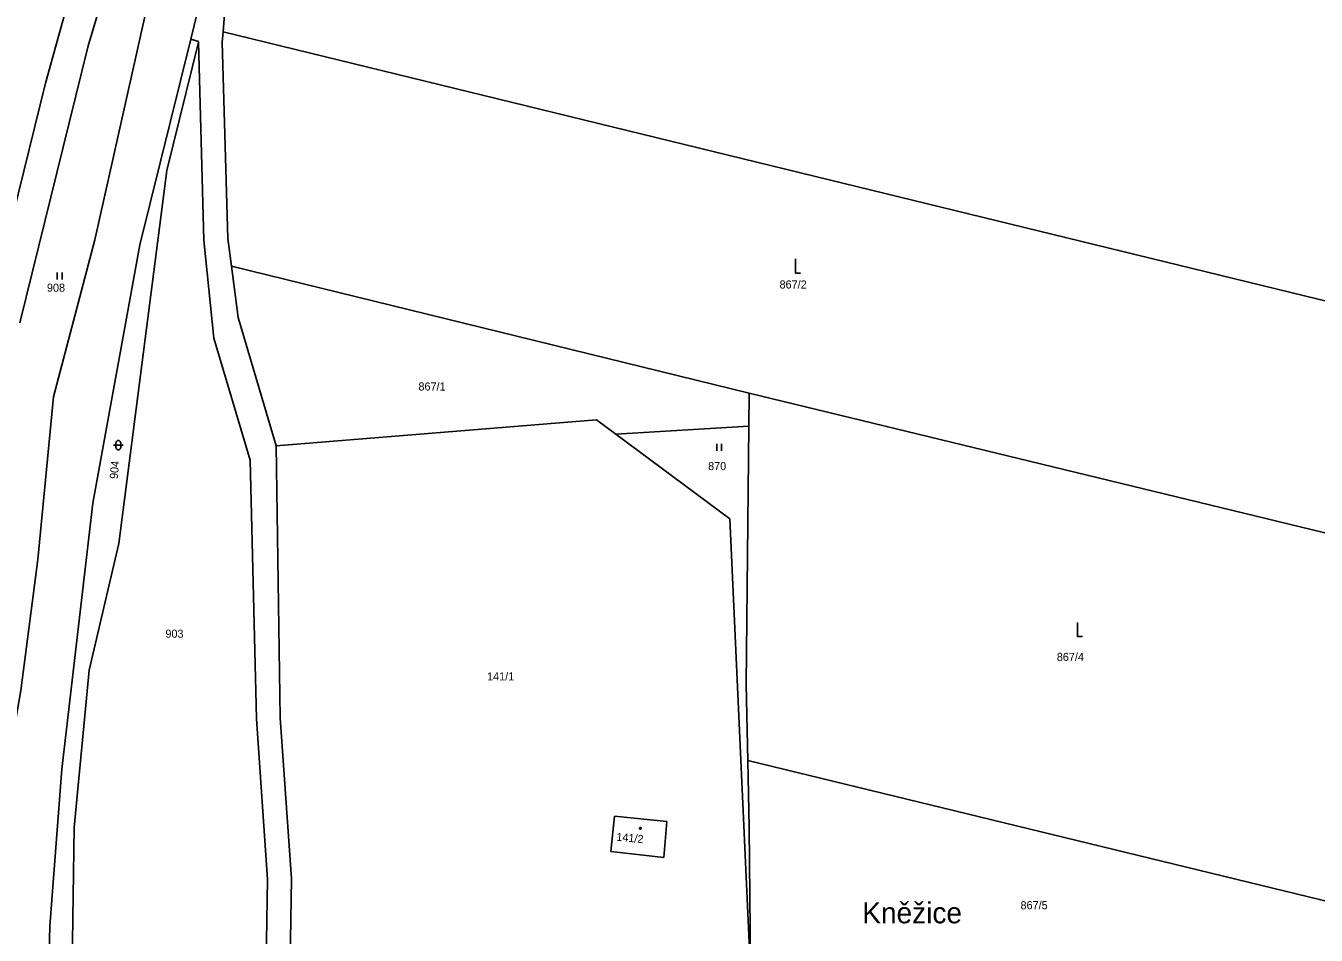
# Model space of a CAD drawing. Extents: x -812394 to -807601, y -1013097 to -1009266.
# Drawn here: x -809883 to -809612.2, y -1010592.7 to -1010401.8 of the extents above; entities that cross this region are included whole.
import ezdxf

# ---------------------------------------------------------------- set-up
doc = ezdxf.new("R2010")
doc.units = 0
for name, color, linetype in [('Default', 7, 'Continuous'), ('KN_HRANICE', 7, 'Continuous'), ('KN_KULTURY', 7, 'Continuous'), ('KN_PARCELY', 7, 'Continuous')]:
    doc.layers.add(name, color=color, linetype=linetype)

# ---------------------------------------------------------------- blocks, each defined once
blk = doc.blocks.new('302')
at = {"layer": 'Default'}
blk.add_lwpolyline([(0, 3), (0, 0), (1, 0)], dxfattribs=at)
blk = doc.blocks.new('306')
at = {"layer": 'Default'}
for p, q in [((-0.5, 1.5), (-0.5, 0)), ((0.5, 0), (0.5, 1.5))]:
    blk.add_line(p, q, dxfattribs=at)
blk = doc.blocks.new('316')
at = {"layer": 'Default'}
for points in [[(-1, 1), (0.27, 1), (1, 1)], [(-0.5, 1.5), (-0.4, 1.79), (-0.15, 1.97), (0.16, 1.97), (0.41, 1.79), (0.51, 1.5), (0.51, 0.5), (0.41, 0.21), (0.16, 0.03), (-0.15, 0.03), (-0.4, 0.21), (-0.5, 0.5), (-0.5, 1.5)]]:
    blk.add_lwpolyline(points, dxfattribs=at)
blk = doc.blocks.new('402')
at = {"layer": 'Default'}
blk.add_lwpolyline([(0.09, 0.15), (0.18, 0), (0.09, -0.15), (-0.09, -0.15), (-0.18, 0), (-0.09, 0.15), (0.09, 0.15)], dxfattribs=at)

msp = doc.modelspace()

# ---------------------------------------------------------------- linework, layer by layer
at = {"layer": 'KN_HRANICE'}
for p, q in [((-809864.27, -1010361.43), (-809878.82, -1010413.89)), ((-809869.89, -1010406.06), (-809858.75, -1010368.45)), ((-809842.4, -1010380.57), (-809848.37, -1010404.67)), ((-809841.57, -1010403.09), (-809840.96, -1010395.38)), ((-809841.74, -1010405.27), (-809841.57, -1010403.09)), ((-809714.42, -1010434.16), (-809841.57, -1010403.09)), ((-809884.23, -1010464.16), (-809869.89, -1010406.06)), ((-809848.37, -1010404.67), (-809859.05, -1010447.8)), ((-809853.38, -1010432.24), (-809846.74, -1010405.27)), ((-809848.37, -1010404.67), (-809846.74, -1010405.14)), ((-809846.74, -1010405.14), (-809846.74, -1010405.27)), ((-809846.74, -1010405.27), (-809845.6, -1010446.84)), ((-809840.6, -1010446.52), (-809841.74, -1010405.27)), ((-809878.82, -1010413.89), (-809894.45, -1010477.13)), ((-809863.41, -1010510.51), (-809853.38, -1010432.24)), ((-809587.27, -1010465.23), (-809714.42, -1010434.16)), ((-809845.6, -1010446.84), (-809843.49, -1010467.38)), ((-809840.6, -1010446.52), (-809839.82, -1010452.31)), ((-809859.05, -1010447.8), (-809868.93, -1010502.05)), ((-809839.82, -1010452.31), (-809838.38, -1010463.06)), ((-809839.82, -1010452.31), (-809731.16, -1010478.93)), ((-809830.46, -1010490), (-809838.38, -1010463.06)), ((-809843.49, -1010467.38), (-809835.86, -1010493.01)), ((-809731.16, -1010478.93), (-809731.23, -1010485.87)), ((-809731.16, -1010478.93), (-809588.81, -1010513.56)), ((-809763.21, -1010484.53), (-809830.46, -1010490)), ((-809759.15, -1010487.55), (-809763.21, -1010484.53)), ((-809731.23, -1010485.87), (-809759.15, -1010487.55)), ((-809731.8, -1010540.09), (-809731.23, -1010485.87)), ((-809830.46, -1010490), (-809829.59, -1010547.11)), ((-809735.22, -1010505.35), (-809759.15, -1010487.55)), ((-809835.86, -1010493.01), (-809834.59, -1010547.32)), ((-809868.93, -1010502.05), (-809875.4, -1010557.89)), ((-809730.9, -1010600.87), (-809735.22, -1010505.35)), ((-809869.64, -1010537.09), (-809863.41, -1010510.51)), ((-809872.78, -1010570.15), (-809869.64, -1010537.09)), ((-809731.49, -1010556.03), (-809731.8, -1010540.09)), ((-809834.59, -1010547.32), (-809832.23, -1010581.05)), ((-809829.59, -1010547.11), (-809827.23, -1010580.92)), ((-809731.22, -1010570.09), (-809731.49, -1010556.03)), ((-809731.49, -1010556.03), (-809591.24, -1010590.16)), ((-809875.4, -1010557.89), (-809877.92, -1010590.8)), ((-809760.19, -1010575.15), (-809759.48, -1010567.72)), ((-809759.48, -1010567.72), (-809748.44, -1010568.84)), ((-809873.36, -1010604.47), (-809872.78, -1010570.15)), ((-809748.44, -1010568.84), (-809749.12, -1010576.39)), ((-809730.9, -1010600.87), (-809731.22, -1010570.09)), ((-809749.12, -1010576.39), (-809760.19, -1010575.15)), ((-809832.23, -1010581.05), (-809832.51, -1010598.19)), ((-809827.23, -1010580.92), (-809827.51, -1010598.06)), ((-809877.92, -1010590.8), (-809879.03, -1010627.62))]:
    msp.add_line(p, q, dxfattribs=at)
msp.add_lwpolyline([(-809898.33, -1010631.14), (-809892.3, -1010585.73), (-809889.06, -1010570.22), (-809883.97, -1010541.36), (-809880.44, -1010513.89), (-809877.14, -1010479.74), (-809868.51, -1010446.75), (-809850.96, -1010368.61), (-809838.06, -1010317.02)], dxfattribs=at)

# ---------------------------------------------------------------- block references
at = {"layer": 'KN_KULTURY'}
for name, p in [('302', (-809721.44, -1010453.78)), ('306', (-809875.85, -1010455.12)), ('316', (-809863.55, -1010490.87)), ('306', (-809737.47, -1010491.07)), ('302', (-809662.28, -1010530.06)), ('402', (-809754.04, -1010570.3))]:
    msp.add_blockref(name, p, dxfattribs=at)

# ---------------------------------------------------------------- texts
at = {"layer": 'KN_PARCELY'}
for s, height, p in [('908', 1.7, (-809878.52, -1010457.66)), ('867/2', 1.7, (-809724.82, -1010456.99)), ('867/1', 1.7, (-809800.58, -1010478.4)), ('870', 1.7, (-809739.81, -1010495.1)), ('903', 1.7, (-809853.67, -1010530.29)), ('867/4', 1.7, (-809666.65, -1010535.16)), ('141/1', 1.7, (-809786.18, -1010539.25)), ('Kněžice', 4.4, (-809707.47, -1010590.23)), ('867/5', 1.7, (-809674.26, -1010587.28))]:
    msp.add_text(s, height=height, dxfattribs=at).set_placement(p)
for s, rotation, p in [('904', 84.74, (-809863.69, -1010497.03)), ('141/2', 354.374, (-809759.12, -1010572.87))]:
    msp.add_text(s, height=1.7, rotation=rotation, dxfattribs=at).set_placement(p)

doc.saveas('drawing.dxf')
